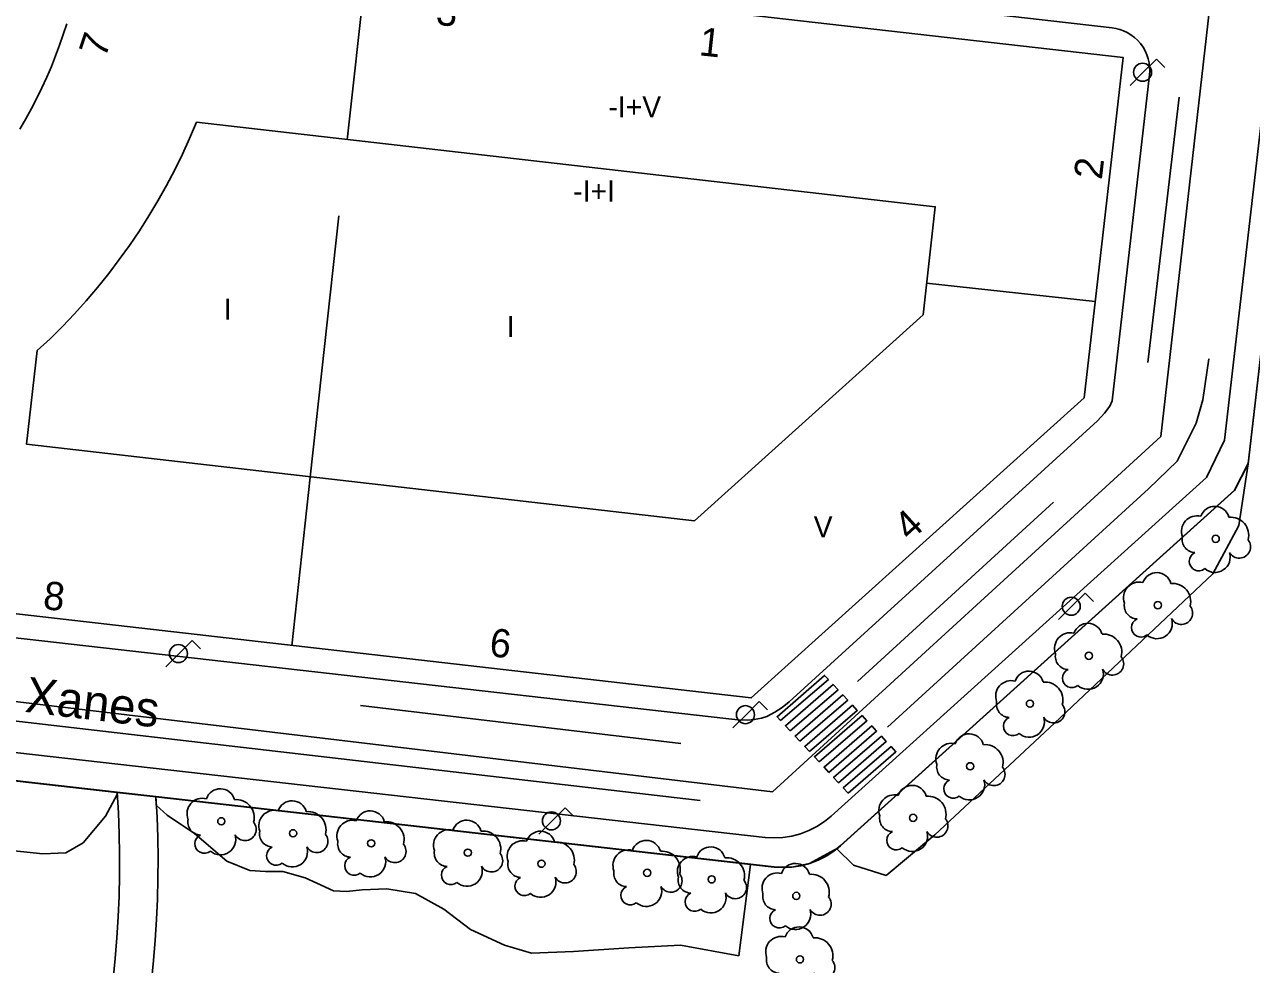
# Model space of a CAD drawing. Extents: x 282771 to 285132, y 4823109 to 4825496.
# Drawn here: x 283212.2 to 283299, y 4823806.7 to 4823873.2 of the extents above; entities that cross this region are included whole.
import ezdxf

# ---------------------------------------------------------------- set-up
doc = ezdxf.new("R2010")
doc.units = 0
for name, color, linetype in [('ACERA-BORDILLO', 7, 'Continuous'), ('ACERA-INTERIOR', 7, 'Continuous'), ('ARBOL', 7, 'Continuous'), ('CALLE-EJE', 7, 'Continuous'), ('CALLE-TEXTO', 7, 'Continuous'), ('EDIFICIO', 7, 'Continuous'), ('FAROLA', 7, 'Continuous'), ('INTERIOR-EDIFICIO', 7, 'Continuous'), ('MEDIANERA', 7, 'Continuous'), ('NUM-PORTAL', 7, 'Continuous'), ('PARQUE-JARDIN-AREA', 7, 'Continuous'), ('PASO-PEATONES', 7, 'Continuous'), ('SENAL-VIARIA', 7, 'Continuous'), ('TXT-ALTURA-EDIFICIO', 7, 'Continuous'), ('ZONA-VERDE', 7, 'Continuous')]:
    doc.layers.add(name, color=color, linetype=linetype)

msp = doc.modelspace()

# ---------------------------------------------------------------- linework, layer by layer
at = {"layer": 'ACERA-BORDILLO'}
for points in [[(283080.791, 4823844.662), (283261.807, 4823824.108), (283262.669, 4823824.015), (283263.37, 4823823.99), (283263.818, 4823824.04), (283264.325, 4823824.142), (283264.707, 4823824.266), (283265.278, 4823824.556), (283265.808, 4823824.902), (283266.292, 4823825.294), (283288.121, 4823845.171), (283288.62, 4823845.721), (283289.001, 4823846.203), (283289.159, 4823846.576), (283291.793, 4823869.652), (283291.812, 4823869.922), (283291.805, 4823870.2), (283291.772, 4823870.486), (283291.709, 4823870.773), (283291.617, 4823871.059), (283291.494, 4823871.339), (283291.341, 4823871.607), (283291.161, 4823871.859), (283290.956, 4823872.092), (283290.729, 4823872.301), (283290.484, 4823872.484), (283290.226, 4823872.639), (283289.96, 4823872.764), (283289.69, 4823872.861), (283289.42, 4823872.931), (283289.153, 4823872.973), (283206.887, 4823882.376)], [(283077.754, 4823836.86), (283264.587, 4823815.706), (283265.207, 4823815.669), (283265.839, 4823815.697), (283266.471, 4823815.792), (283267.093, 4823815.956), (283267.693, 4823816.185), (283268.263, 4823816.475), (283268.793, 4823816.82), (283269.275, 4823817.212), (283295.839, 4823841.155), (283297.113, 4823843.795), (283300.154, 4823870.152)]]:
    msp.add_lwpolyline(points, dxfattribs=at)
at = {"layer": 'ACERA-INTERIOR'}
for points in [[(283221.473, 4823818.589), (283265.236, 4823813.618), (283265.857, 4823813.58), (283266.489, 4823813.608), (283267.122, 4823813.703), (283267.745, 4823813.867), (283268.346, 4823814.096), (283268.917, 4823814.386), (283269.447, 4823814.731), (283269.93, 4823815.123), (283297.821, 4823840.264), (283298.794, 4823842.159), (283302.014, 4823870.108)], [(283174.055, 4823823.974), (283218.728, 4823818.9)], [(283214.598, 4823781.193), (283214.71, 4823783.931), (283215.101, 4823787.84), (283215.771, 4823792.141), (283216.547, 4823795.556), (283216.903, 4823796.979), (283217.231, 4823798.41), (283217.53, 4823799.85), (283217.8, 4823801.297), (283218.041, 4823802.75), (283218.253, 4823804.209), (283218.435, 4823805.672), (283218.587, 4823807.14), (283218.709, 4823808.609), (283218.801, 4823810.081), (283218.864, 4823811.554), (283218.896, 4823813.027), (283218.899, 4823814.499), (283218.871, 4823815.969), (283218.814, 4823817.436), (283218.728, 4823818.9)], [(283217.696, 4823781.584), (283217.445, 4823784.545), (283217.501, 4823786.556), (283217.836, 4823788.957), (283218.562, 4823792.42), (283219.354, 4823795.556), (283219.693, 4823796.963), (283220.005, 4823798.377), (283220.29, 4823799.799), (283220.548, 4823801.227), (283220.778, 4823802.661), (283220.981, 4823804.1), (283221.156, 4823805.544), (283221.304, 4823806.99), (283221.423, 4823808.44), (283221.514, 4823809.891), (283221.577, 4823811.343), (283221.612, 4823812.795), (283221.619, 4823814.246), (283221.598, 4823815.696), (283221.549, 4823817.144), (283221.473, 4823818.589)], [(283218.728, 4823818.9), (283221.473, 4823818.589)]]:
    msp.add_lwpolyline(points, dxfattribs=at)
at = {"layer": 'ARBOL'}
for centre in [(283296.487, 4823836.826), (283292.387, 4823832.136), (283287.507, 4823828.556), (283283.337, 4823825.166), (283279.107, 4823820.736), (283275.067, 4823817.086), (283226.097, 4823816.846), (283231.177, 4823815.996), (283236.707, 4823815.286), (283243.547, 4823814.626), (283248.757, 4823813.846), (283256.247, 4823813.196), (283260.807, 4823812.736), (283266.797, 4823811.566), (283267.057, 4823807.076)]:
    msp.add_circle(centre, 0.255, dxfattribs=at)
for centre, radius, start, end in [((283296.417, 4823838.086), 1.038, 15.64228, 161.38435), ((283295.157, 4823837.356), 1.097, 75.4318, 200.55608), ((283297.547, 4823837.086), 1.272, 345.03273, 95.79925), ((283295.047, 4823836.786), 0.935, 168.59898, 268.13236), ((283298.157, 4823836.256), 0.797, 208.96246, 38.99103), ((283295.287, 4823835.236), 0.672, 113.73672, 309.4725), ((283296.427, 4823835.536), 1.086, 228.95447, 17.92796), ((283292.317, 4823833.396), 1.038, 15.64228, 161.38435), ((283291.057, 4823832.666), 1.097, 75.4318, 200.55608), ((283293.447, 4823832.396), 1.272, 345.03273, 95.79925), ((283290.947, 4823832.096), 0.935, 168.59898, 268.13236), ((283294.057, 4823831.566), 0.797, 208.96246, 38.99103), ((283287.437, 4823829.816), 1.038, 15.64228, 161.38435), ((283291.187, 4823830.546), 0.672, 113.73672, 309.4725), ((283292.327, 4823830.846), 1.086, 228.95447, 17.92796), ((283286.177, 4823829.086), 1.097, 75.4318, 200.55608), ((283288.567, 4823828.816), 1.272, 345.03273, 95.79925), ((283286.067, 4823828.516), 0.935, 168.59898, 268.13236), ((283289.177, 4823827.986), 0.797, 208.96246, 38.99103), ((283283.267, 4823826.426), 1.038, 15.64228, 161.38435), ((283286.307, 4823826.966), 0.672, 113.73672, 309.4725), ((283287.447, 4823827.266), 1.086, 228.95447, 17.92796), ((283282.007, 4823825.696), 1.097, 75.4318, 200.55608), ((283284.397, 4823825.426), 1.272, 345.03273, 95.79925), ((283281.897, 4823825.126), 0.935, 168.59898, 268.13236), ((283285.007, 4823824.596), 0.797, 208.96246, 38.99103), ((283282.137, 4823823.576), 0.672, 113.73672, 309.4725), ((283283.277, 4823823.876), 1.086, 228.95447, 17.92796), ((283279.037, 4823821.996), 1.038, 15.64228, 161.38435), ((283277.777, 4823821.266), 1.097, 75.4318, 200.55608), ((283280.167, 4823820.996), 1.272, 345.03273, 95.79925), ((283277.667, 4823820.696), 0.935, 168.59898, 268.13236), ((283280.777, 4823820.166), 0.797, 208.96246, 38.99103), ((283226.027, 4823818.106), 1.038, 15.64228, 161.38435), ((283274.997, 4823818.346), 1.038, 15.64228, 161.38435), ((283277.907, 4823819.146), 0.672, 113.73672, 309.4725), ((283279.047, 4823819.446), 1.086, 228.95447, 17.92796), ((283224.767, 4823817.376), 1.097, 75.4318, 200.55608), ((283227.157, 4823817.106), 1.272, 345.03273, 95.79925), ((283231.107, 4823817.256), 1.038, 15.64228, 161.38435), ((283273.737, 4823817.616), 1.097, 75.4318, 200.55608), ((283276.127, 4823817.346), 1.272, 345.03273, 95.79925), ((283229.847, 4823816.526), 1.097, 75.4318, 200.55608), ((283232.237, 4823816.256), 1.272, 345.03273, 95.79925), ((283236.637, 4823816.546), 1.038, 15.64228, 161.38435), ((283224.657, 4823816.806), 0.935, 168.59898, 268.13236), ((283227.767, 4823816.276), 0.797, 208.96246, 38.99103), ((283235.377, 4823815.816), 1.097, 75.4318, 200.55608), ((283237.767, 4823815.546), 1.272, 345.03273, 95.79925), ((283243.477, 4823815.886), 1.038, 15.64228, 161.38435), ((283273.627, 4823817.046), 0.935, 168.59898, 268.13236), ((283276.737, 4823816.516), 0.797, 208.96246, 38.99103), ((283224.897, 4823815.256), 0.672, 113.73672, 309.4725), ((283226.037, 4823815.556), 1.086, 228.95447, 17.92796), ((283229.737, 4823815.956), 0.935, 168.59898, 268.13236), ((283232.847, 4823815.426), 0.797, 208.96246, 38.99103), ((283242.217, 4823815.156), 1.097, 75.4318, 200.55608), ((283244.607, 4823814.886), 1.272, 345.03273, 95.79925), ((283248.687, 4823815.106), 1.038, 15.64228, 161.38435), ((283273.867, 4823815.496), 0.672, 113.73672, 309.4725), ((283275.007, 4823815.796), 1.086, 228.95447, 17.92796), ((283229.977, 4823814.406), 0.672, 113.73672, 309.4725), ((283231.117, 4823814.706), 1.086, 228.95447, 17.92796), ((283235.267, 4823815.246), 0.935, 168.59898, 268.13236), ((283238.377, 4823814.716), 0.797, 208.96246, 38.99103), ((283242.107, 4823814.586), 0.935, 168.59898, 268.13236), ((283247.427, 4823814.376), 1.097, 75.4318, 200.55608), ((283249.817, 4823814.106), 1.272, 345.03273, 95.79925), ((283254.917, 4823813.726), 1.097, 75.4318, 200.55608), ((283256.177, 4823814.456), 1.038, 15.64228, 161.38435), ((283257.307, 4823813.456), 1.272, 345.03273, 95.79925), ((283260.737, 4823813.996), 1.038, 15.64228, 161.38435), ((283235.507, 4823813.696), 0.672, 113.73672, 309.4725), ((283236.647, 4823813.996), 1.086, 228.95447, 17.92796), ((283245.217, 4823814.056), 0.797, 208.96246, 38.99103), ((283247.317, 4823813.806), 0.935, 168.59898, 268.13236), ((283259.477, 4823813.266), 1.097, 75.4318, 200.55608), ((283261.867, 4823812.996), 1.272, 345.03273, 95.79925), ((283266.727, 4823812.826), 1.038, 15.64228, 161.38435), ((283242.347, 4823813.036), 0.672, 113.73672, 309.4725), ((283243.487, 4823813.336), 1.086, 228.95447, 17.92796), ((283250.427, 4823813.276), 0.797, 208.96246, 38.99103), ((283254.807, 4823813.156), 0.935, 168.59898, 268.13236), ((283257.917, 4823812.626), 0.797, 208.96246, 38.99103), ((283265.467, 4823812.096), 1.097, 75.4318, 200.55608), ((283267.857, 4823811.826), 1.272, 345.03273, 95.79925), ((283247.557, 4823812.256), 0.672, 113.73672, 309.4725), ((283248.697, 4823812.556), 1.086, 228.95447, 17.92796), ((283255.047, 4823811.606), 0.672, 113.73672, 309.4725), ((283256.187, 4823811.906), 1.086, 228.95447, 17.92796), ((283259.367, 4823812.696), 0.935, 168.59898, 268.13236), ((283262.477, 4823812.166), 0.797, 208.96246, 38.99103), ((283259.607, 4823811.146), 0.672, 113.73672, 309.4725), ((283260.747, 4823811.446), 1.086, 228.95447, 17.92796), ((283265.357, 4823811.526), 0.935, 168.59898, 268.13236), ((283268.467, 4823810.996), 0.797, 208.96246, 38.99103), ((283265.597, 4823809.976), 0.672, 113.73672, 309.4725), ((283266.737, 4823810.276), 1.086, 228.95447, 17.92796), ((283265.727, 4823807.606), 1.097, 75.4318, 200.55608), ((283266.987, 4823808.336), 1.038, 15.64228, 161.38435), ((283268.117, 4823807.336), 1.272, 345.03273, 95.79925), ((283265.617, 4823807.036), 0.935, 168.59898, 268.13236), ((283268.727, 4823806.506), 0.797, 208.96246, 38.99103)]:
    msp.add_arc(centre, radius, start, end, dxfattribs=at)
at = {"layer": 'CALLE-EJE'}
msp.add_lwpolyline([(283058.898, 4823903.605), (283055.289, 4823871.265), (283076.539, 4823841.396), (283265.107, 4823818.926), (283292.597, 4823844.076), (283296.257, 4823876.185)], dxfattribs=at)
at = {"layer": 'EDIFICIO'}
for points in [[(283240.327, 4823876.535), (283289.927, 4823870.875), (283288.137, 4823855.226), (283287.177, 4823846.806), (283263.607, 4823825.576), (283235.097, 4823828.826), (283177.578, 4823835.406)], [(283211.831, 4823865.801), (283212.254, 4823866.527), (283212.657, 4823867.259), (283213.04, 4823867.997), (283213.403, 4823868.74), (283213.745, 4823869.488), (283214.067, 4823870.24), (283214.651, 4823871.75), (283215.155, 4823873.266)]]:
    msp.add_lwpolyline(points, dxfattribs=at)
at = {"layer": 'FAROLA'}
for p, q in [((283292.291, 4823870.763), (283291.351, 4823869.833)), ((283292.881, 4823870.173), (283292.291, 4823870.763)), ((283291.351, 4823869.833), (283290.421, 4823868.893)), ((283287.237, 4823832.986), (283286.297, 4823832.056)), ((283287.827, 4823832.396), (283287.237, 4823832.986)), ((283286.297, 4823832.056), (283285.367, 4823831.116)), ((283224.045, 4823829.638), (283223.105, 4823828.708)), ((283224.635, 4823829.048), (283224.045, 4823829.638)), ((283223.105, 4823828.708), (283222.175, 4823827.768)), ((283264.181, 4823825.317), (283263.241, 4823824.387)), ((283264.771, 4823824.727), (283264.181, 4823825.317)), ((283263.241, 4823824.387), (283262.311, 4823823.447)), ((283250.447, 4823817.806), (283249.507, 4823816.876)), ((283251.037, 4823817.216), (283250.447, 4823817.806)), ((283249.507, 4823816.876), (283248.577, 4823815.936))]:
    msp.add_line(p, q, dxfattribs=at)
for centre, radius in [((283291.311, 4823869.833), 0.638), ((283286.257, 4823832.056), 0.637), ((283223.065, 4823828.708), 0.637), ((283263.201, 4823824.387), 0.637), ((283249.467, 4823816.876), 0.637)]:
    msp.add_circle(centre, radius, dxfattribs=at)
at = {"layer": 'INTERIOR-EDIFICIO'}
msp.add_lwpolyline([(283224.334, 4823866.291), (283223.854, 4823865.156), (283223.341, 4823864.032), (283222.797, 4823862.919), (283222.22, 4823861.821), (283221.612, 4823860.737), (283220.973, 4823859.669), (283220.304, 4823858.618), (283219.606, 4823857.586), (283218.879, 4823856.575), (283218.125, 4823855.584), (283217.343, 4823854.615), (283216.537, 4823853.67), (283215.705, 4823852.749), (283214.85, 4823851.853), (283213.972, 4823850.983), (283213.073, 4823850.14), (283212.317, 4823843.516), (283259.597, 4823838.106), (283275.767, 4823852.676), (283276.637, 4823860.316), (283224.334, 4823866.291)], dxfattribs=at)
at = {"layer": 'MEDIANERA'}
for points in [[(283236.327, 4823876.975), (283235.017, 4823865.045)], [(283232.397, 4823841.192), (283234.426, 4823859.666)], [(283276.022, 4823854.914), (283287.952, 4823853.605)], [(283232.397, 4823841.192), (283231.097, 4823829.262)]]:
    msp.add_lwpolyline(points, dxfattribs=at)
at = {"layer": 'PARQUE-JARDIN-AREA'}
msp.add_lwpolyline([(283127.005, 4823829.171), (283176.123, 4823823.637), (283176.132, 4823823.718), (283218.713, 4823818.882), (283221.458, 4823818.57), (283263.559, 4823813.789), (283265.222, 4823813.601), (283266.475, 4823813.59), (283267.731, 4823813.849), (283269.751, 4823814.962), (283269.916, 4823815.106), (283297.808, 4823840.247), (283298.781, 4823842.142), (283302.014, 4823870.108)], dxfattribs=at)
at = {"layer": 'PASO-PEATONES'}
for points in [[(283265.686, 4823823.966), (283265.435, 4823824.235), (283268.806, 4823827.163), (283269.069, 4823826.883)], [(283266.369, 4823823.235), (283266.028, 4823823.6), (283269.41, 4823826.517), (283269.752, 4823826.151)], [(283267.052, 4823822.503), (283266.711, 4823822.869), (283270.093, 4823825.785), (283270.435, 4823825.42)], [(283267.735, 4823821.771), (283267.394, 4823822.137), (283270.776, 4823825.054), (283271.117, 4823824.688)], [(283268.418, 4823821.04), (283268.076, 4823821.406), (283271.459, 4823824.322), (283271.8, 4823823.956)], [(283269.101, 4823820.308), (283268.759, 4823820.674), (283272.142, 4823823.591), (283272.483, 4823823.225)], [(283269.784, 4823819.577), (283269.442, 4823819.943), (283272.825, 4823822.859), (283273.166, 4823822.493)], [(283270.467, 4823818.845), (283270.125, 4823819.211), (283273.508, 4823822.128), (283273.849, 4823821.762)]]:
    msp.add_lwpolyline(points, close=True, dxfattribs=at)
at = {"layer": 'SENAL-VIARIA'}
for points in [[(283293.891, 4823868.068), (283291.681, 4823849.298)], [(283273.257, 4823823.511), (283291.737, 4823840.352), (283293.759, 4823842.328), (283295.114, 4823845.004), (283295.571, 4823846.67), (283296, 4823849.547)], [(283285.001, 4823839.428), (283271.13, 4823826.727)], [(283259.986, 4823818.307), (283177.434, 4823827.889)], [(283258.623, 4823822.352), (283235.959, 4823825.034)]]:
    msp.add_lwpolyline(points, dxfattribs=at)
at = {"layer": 'ZONA-VERDE'}
for p, q in [((283297.808, 4823840.247), (283298.781, 4823842.142)), ((283298.781, 4823842.142), (283298.113, 4823837.759)), ((283269.916, 4823815.106), (283297.808, 4823840.247)), ((283298.113, 4823837.759), (283297.413, 4823836.449)), ((283297.413, 4823836.449), (283296.293, 4823834.339)), ((283296.293, 4823834.339), (283285.073, 4823823.779)), ((283176.132, 4823823.718), (283218.713, 4823818.882)), ((283285.073, 4823823.779), (283276.603, 4823815.898)), ((283218.723, 4823818.729), (283217.891, 4823817.214)), ((283218.713, 4823818.882), (283218.723, 4823818.729)), ((283221.493, 4823817.99), (283221.458, 4823818.57)), ((283221.458, 4823818.57), (283263.559, 4823813.789)), ((283222.254, 4823817.279), (283221.493, 4823817.99)), ((283217.891, 4823817.214), (283216.328, 4823815.324)), ((283224.208, 4823815.976), (283222.254, 4823817.279)), ((283226.487, 4823814.021), (283224.208, 4823815.976)), ((283276.603, 4823815.898), (283273.153, 4823813.018)), ((283213.462, 4823814.542), (283210.271, 4823814.868)), ((283216.328, 4823815.324), (283215.09, 4823814.607)), ((283269.673, 4823814.898), (283269.751, 4823814.962)), ((283269.679, 4823814.891), (283269.673, 4823814.898)), ((283270.853, 4823813.738), (283269.679, 4823814.891)), ((283269.751, 4823814.962), (283269.916, 4823815.106)), ((283215.09, 4823814.607), (283213.462, 4823814.542)), ((283228.115, 4823813.369), (283226.487, 4823814.021)), ((283229.222, 4823813.304), (283228.115, 4823813.369)), ((283230.46, 4823813.304), (283229.222, 4823813.304)), ((283232.023, 4823812.848), (283230.46, 4823813.304)), ((283263.559, 4823813.789), (283262.728, 4823807.333)), ((283273.153, 4823813.018), (283270.853, 4823813.738)), ((283232.869, 4823812.457), (283232.023, 4823812.848)), ((283234.041, 4823811.936), (283232.869, 4823812.457)), ((283234.497, 4823811.903), (283234.041, 4823811.936)), ((283234.953, 4823811.871), (283234.497, 4823811.903)), ((283236.06, 4823812.001), (283234.953, 4823811.871)), ((283237.819, 4823812.066), (283236.06, 4823812.001)), ((283239.838, 4823811.74), (283237.819, 4823812.066)), ((283241.856, 4823810.633), (283239.838, 4823811.74)), ((283243.745, 4823809.199), (283241.856, 4823810.633)), ((283246.155, 4823808.092), (283243.745, 4823809.199)), ((283248.043, 4823807.505), (283246.155, 4823808.092)), ((283254.946, 4823807.896), (283251.039, 4823807.636)), ((283258.593, 4823808.092), (283254.946, 4823807.896)), ((283262.728, 4823807.333), (283258.593, 4823808.092)), ((283251.039, 4823807.636), (283248.043, 4823807.505))]:
    msp.add_line(p, q, dxfattribs=at)

# ---------------------------------------------------------------- texts
at = {"layer": 'CALLE-TEXTO'}
msp.add_text('Calle Desfiladero Les Xanes', height=2.5, rotation=353.2047, dxfattribs=at).set_placement((283179.664, 4823828.461))
at = {"layer": 'NUM-PORTAL'}
for s, rotation, p in [('3', 353.76004, (283241.236, 4823873.205)), ('1', 353.76004, (283259.866, 4823871.04)), ('7', 71.70689, (283217.881, 4823870.769)), ('2', 83.42004, (283288.422, 4823862.19)), ('4', 42.30004, (283274.845, 4823836.599)), ('8', 353.76004, (283213.424, 4823831.866)), ('6', 353.76004, (283245.02, 4823828.53))]:
    msp.add_text(s, height=2, rotation=rotation, dxfattribs=at).set_placement(p)
at = {"layer": 'TXT-ALTURA-EDIFICIO'}
for s, p in [('-I+V', (283253.496, 4823866.636)), ('-I+I', (283251.004, 4823860.678)), ('I', (283226.279, 4823852.324)), ('I', (283246.303, 4823851.095)), ('V', (283268.028, 4823836.926))]:
    msp.add_text(s, height=1.5, rotation=0.00004, dxfattribs=at).set_placement(p)

doc.saveas('drawing.dxf')
